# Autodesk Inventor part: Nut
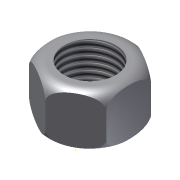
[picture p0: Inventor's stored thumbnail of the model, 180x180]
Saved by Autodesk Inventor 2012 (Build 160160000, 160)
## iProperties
Created: 2010-03
Part Number: Nut
Document SubType Name: Modeling
Designer: bhakira
Density: 1 g/cm^3
Material: Default
Author: bhakira
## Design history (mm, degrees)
sketch "Sketch1"
  geometry: L1 (0, 17.321)-(15, 8.66); L2 (15, 8.66)-(15, -8.66); L3 (15, -8.66)-(0, -17.321); L4 (0, -17.321)-(-15, -8.66); L5 (-15, -8.66)-(-15, 8.66); L6 (-15, 8.66)-(0, 17.321); 2 further points
  constraints: 12 end point, 1 coincident, 13 other
  dimensions: "d0" = 30 distance between parallel lines of L2 L5
extrude "Extrusion1" new body sketch "Sketch1" distance "d1" = 20; taper "d2" = 0 deg
sketch "Sketch2"
  geometry: L1 (0, 17.321)-(-15, 8.66) reference; L2 (-15, 8.66)-(-15, -8.66) reference; L3 (-15, -8.66)-(0, -17.321) reference; L4 (0, -17.321)-(15, -8.66) reference; L5 (15, -8.66)-(15, 8.66) reference; L6 (15, 8.66)-(0, 17.321) reference
sketch "Sketch3"
  geometry: C1 r 10 at (0, 0); 1 further point
  constraints: 1 centre point, 1 coincident
  dimensions: "d4" = 20 diameter of C1
extrude "Extrusion2" cut sketch "Sketch3" stored distance "d5" = 15; taper "d6" = 0 deg
thread "Thread1" dims "d7" = 10, "d8" = 0
sketch "Sketch5"
  geometry: L1 (-17.321, 20)-(-8.66, 20) reference; L2 (-17.321, 20)-(-8.66, 20) reference; L3 (-8.66, 0)-(-8.66, 20) reference; L4 (-17.321, 0)-(-8.66, 0) reference; L5 (-17.321, 0)-(-17.321, 20) reference; L6 (0, -8)-(0, 24); L7 (-12.035, 20)-(-17.321, 20); A1 r 5.286 centre (-12.035, 14.714) between (-12.035, 20) and (-17.321, 14.714); 1 further point
  constraints: 4 end point, 3 tangent, 2 point on circle, 2 point on line, 1 centre point, 1 collinear, 1 parallel
revolve "Revolution1" sketch "Sketch5" stored, may be unused: angle "d16" = 90 deg
sketch "Sketch6"
  geometry: 1 further point
workplane "Work Plane1"
mirror "Mirror1"
body "Solid1"
node "Projected Loop1"
